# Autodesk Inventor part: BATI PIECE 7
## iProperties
Created: 2004-11
Part Number: BATI PIECE 7
Document SubType Name: Modeling
Designer: Bruno
Manufacturer: Standard
Standards Organization: Custom
Author: Bruno
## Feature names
1. Base1
